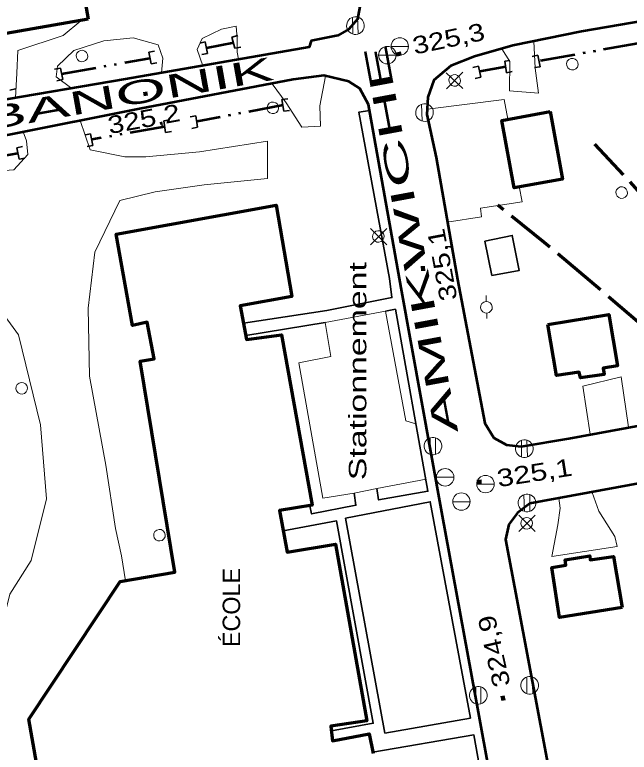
# Model space of a CAD drawing. Extents: x 240591 to 242335, y 5323482 to 5326937.
# Drawn here: x 241079.8 to 241185.4, y 5324850.8 to 5324977.7 of the extents above; entities that cross this region are included whole.
import ezdxf
from ezdxf.enums import TextEntityAlignment as Align

# ---------------------------------------------------------------- set-up
doc = ezdxf.new("R2010")
doc.units = 0
doc.header["$LTSCALE"] = 1.2
doc.linetypes.add('DASH_DOUBLE_DOT', pattern=[9.2, 5, -1.2, 0.3, -1.2, 0.3, -1.2])
doc.linetypes.add('LONG_DASHED', pattern=[7.5, 6, -1.5])
for name, color, linetype, lineweight in [('19', 7, 'Continuous', 13), ('21', 7, 'Continuous', 53), ('22', 7, 'LONG_DASHED', 70), ('26', 7, 'Continuous', 35), ('3', 7, 'Continuous', 140), ('31', 7, 'Continuous', 70), ('36', 7, 'Continuous', 13), ('4', 7, 'DASH_DOUBLE_DOT', 53), ('52', 7, 'Continuous', 13)]:
    doc.layers.add(name, color=color, linetype=linetype, lineweight=lineweight)

msp = doc.modelspace()

# ---------------------------------------------------------------- linework, layer by layer
at = {"layer": '19'}
for points in [[(241079.9, 5324963.4), (241080.1, 5324967.6), (241080.3, 5324971.5), (241088.1, 5324974.1), (241091.1, 5324976.6), (241091.1, 5324976.7)], [(241112.1, 5324968.9), (241111.1, 5324971.7), (241112, 5324973.6), (241115.3, 5324975.2), (241117.8, 5324975.7), (241118, 5324973.6), (241118, 5324971.2), (241118.2, 5324970)], [(241089.6, 5324965), (241086.9, 5324967), (241087.1, 5324968.8), (241089.9, 5324971.5), (241095.1, 5324973.2), (241100.1, 5324973.7), (241104.4, 5324972.5), (241105.2, 5324970.2), (241105, 5324967.7)], [(241169, 5324973.1), (241169.2, 5324968.5), (241169.8, 5324964.2), (241164.8, 5324964.6), (241164.9, 5324969.6), (241163.5, 5324971.8)], [(241133.2, 5324967.1), (241132.2, 5324962), (241132.3, 5324958.5), (241129.1, 5324958.3), (241126.4, 5324962.5), (241124, 5324965.8)], [(241150.7, 5324961.4), (241163.9, 5324963.1), (241164.5, 5324959.7)], [(241091, 5324959.5), (241092.7, 5324954.4), (241098.7, 5324953.2), (241102.3, 5324953.2), (241111.5, 5324954.1), (241123.2, 5324955.9), (241123.2, 5324949.5), (241112.3, 5324948.4), (241103.9, 5324947.2), (241097.8, 5324945.7)], [(241066.2, 5324954.9), (241068, 5324951.1), (241073.2, 5324950.5), (241079.6, 5324951), (241082, 5324953.6), (241081.8, 5324956), (241081.2, 5324957.5)], [(241166.5, 5324948.1), (241167, 5324945.5), (241159.8, 5324944.4), (241160, 5324942.9), (241154.1, 5324942)], [(241097.8, 5324945.7), (241093.5, 5324936.8), (241092.4, 5324927.2), (241092.6, 5324915.5), (241095.4, 5324900.2), (241097.1, 5324889.3), (241098.1, 5324884.6), (241098.8, 5324880.3)], [(241075.5, 5324941.5), (241076.7, 5324934.6), (241076.5, 5324927.9), (241080.4, 5324922.6), (241084.2, 5324907.1), (241085.2, 5324894.4), (241082.6, 5324883.8), (241078.9, 5324878), (241076.7, 5324869.2), (241076, 5324856.2), (241076.8, 5324843.7), (241077, 5324835.7), (241077.1, 5324826.8), (241077.4, 5324818)], [(241178.7, 5324905.5), (241177.4, 5324913.8), (241184, 5324915.4), (241185.3, 5324906.7)], [(241179, 5324895.5), (241180.2, 5324892.3), (241182.9, 5324887.9), (241183.3, 5324886.2), (241172.1, 5324884.5), (241173.1, 5324889.9), (241173.5, 5324892.8), (241173.3, 5324894.5)]]:
    msp.add_lwpolyline(points, dxfattribs=at)
at = {"layer": '21'}
for points in [[(241060.9, 5325030.7), (241094, 5325036.4), (241114.9, 5325040.2), (241130.2, 5325042.8), (241134.5, 5325040.3), (241135.6, 5325038.3), (241136.6, 5325024.1), (241139.2, 5324979.7), (241138.7, 5324976.9), (241137.2, 5324975.2), (241135.3, 5324974.1), (241130.7, 5324973.2), (241130.4, 5324972.1), (241098.8, 5324966.6), (241075.9, 5324962.7)], [(241272, 5324952.9), (241262, 5324986.1), (241258.6, 5324988.2), (241254.5, 5324988.5), (241240.4, 5324986.1), (241209.7, 5324980.4), (241177.2, 5324974.8), (241165.4, 5324972.4), (241158.8, 5324970.5), (241154.7, 5324968.9), (241151.8, 5324966.4), (241150.8, 5324963.5), (241150.6, 5324960.5), (241152.2, 5324953.1), (241155.9, 5324932.1)], [(241146.2, 5324930.7), (241140.6, 5324962.2), (241139.1, 5324965), (241137.2, 5324966.2), (241132.9, 5324967.2), (241127.6, 5324966.5), (241101.2, 5324961.5), (241078.8, 5324957), (241046.6, 5324951.6), (241029.4, 5324948.7), (241025.8, 5324947.9), (241023.9, 5324946.7), (241023.1, 5324945.8), (241022.8, 5324944.1)], [(241155.9, 5324932.1), (241160.6, 5324907.4), (241162.1, 5324904.9), (241164.3, 5324903.7), (241166.8, 5324903.4), (241175, 5324904.8), (241207.1, 5324910.7), (241234.4, 5324915.6), (241273.7, 5324922.7), (241275.7, 5324923.8), (241277.1, 5324925.6), (241278.4, 5324929.2)], [(241184.4, 5324723.6), (241184.3, 5324723.9), (241183.8, 5324726), (241180.3, 5324744.6), (241173.9, 5324779.1), (241167.8, 5324812.1), (241159.6, 5324857.1), (241153.2, 5324892.1), (241146.2, 5324930.7)], [(241283.2, 5324909.1), (241281.1, 5324911.9), (241278.1, 5324913.5), (241273.7, 5324913), (241249.5, 5324908.6), (241202.6, 5324899.9), (241168.3, 5324893.6), (241166.2, 5324892), (241164.7, 5324890), (241164.1, 5324887.4), (241165.7, 5324879.2), (241174.6, 5324831.6), (241176.7, 5324829.5), (241178.9, 5324828.5), (241182.8, 5324828.5), (241200.3, 5324831.7), (241239.9, 5324838.8), (241289.9, 5324848.1), (241291.7, 5324849.9), (241292.5, 5324851.5), (241293.4, 5324855.4)]]:
    msp.add_lwpolyline(points, dxfattribs=at)
at = {"layer": '22', "linetype": 'Continuous', "lineweight": 35}
msp.add_line((241133.1, 5324924.7), (241119.5, 5324922.5), dxfattribs=at)
for points in [[(241144.2, 5324932.3), (241138.9, 5324960.9), (241140.8, 5324961.2)], [(241119.1, 5324924.6), (241133.4, 5324926.8), (241144.6, 5324929), (241144.2, 5324932.3)], [(241142, 5324896.2), (241142.3, 5324894.2), (241150.8, 5324895.7), (241145.2, 5324927), (241143.5, 5324926.7)], [(241130.5, 5324893.2), (241130.8, 5324891.8), (241138.4, 5324893.3), (241138.1, 5324895.4)], [(241134.2, 5324854.5), (241141.4, 5324855.8), (241135.1, 5324890.6), (241125.9, 5324888.9)], [(241184.1, 5324724.9), (241182.1, 5324724.6), (241172.5, 5324777.8), (241161.8, 5324836.5), (241158.7, 5324853.8), (241141.3, 5324850.8)]]:
    msp.add_lwpolyline(points, dxfattribs=at)
at = {"layer": '22'}
for points in [[(241179.4, 5324955.4), (241185.5, 5324948.9), (241190.6, 5324943.1), (241195.7, 5324938.9), (241201, 5324933.5), (241205.6, 5324927.3)], [(241192.9, 5324918), (241192.9, 5324918), (241187.3, 5324924.5), (241178.6, 5324931.9), (241170.8, 5324938.5), (241162.8, 5324944.9)]]:
    msp.add_lwpolyline(points, dxfattribs=at)
at = {"layer": '22', "linetype": 'Continuous', "lineweight": 35}
msp.add_lwpolyline([(241136.6, 5324891.1), (241151.2, 5324893.9), (241158.1, 5324856.7), (241143.4, 5324854.1)], close=True, dxfattribs=at)
at = {"layer": '26'}
for p, q in [((241117.1, 5324973.8), (241118.1, 5324974.1)), ((241117.6, 5324971.9), (241117.1, 5324973.8)), ((241112.5, 5324973), (241111.6, 5324972.8)), ((241112.5, 5324973), (241112.9, 5324971)), ((241117.6, 5324971.9), (241118.6, 5324972.1)), ((241102.8, 5324971.2), (241103.8, 5324971.4)), ((241103.2, 5324969.2), (241102.8, 5324971.2)), ((241112.9, 5324971), (241111.9, 5324970.8)), ((241164, 5324969.7), (241164.9, 5324969.8)), ((241164.3, 5324967.7), (241164, 5324969.7)), ((241169.7, 5324970.7), (241168.7, 5324970.5)), ((241169.7, 5324970.7), (241170.1, 5324968.7)), ((241087.6, 5324968.5), (241086.6, 5324968.3)), ((241087.6, 5324968.5), (241088, 5324966.5)), ((241103.2, 5324969.2), (241104.2, 5324969.4)), ((241159.5, 5324968.8), (241158.5, 5324968.6)), ((241159.5, 5324968.8), (241159.9, 5324966.9)), ((241170.1, 5324968.7), (241169.1, 5324968.6)), ((241164.3, 5324967.7), (241165.3, 5324967.9)), ((241088, 5324966.5), (241087, 5324966.3)), ((241159.9, 5324966.9), (241158.9, 5324966.7)), ((241078.9, 5324964.7), (241079.9, 5324964.9)), ((241125.7, 5324963.1), (241126.7, 5324963.2)), ((241126, 5324961.1), (241125.7, 5324963.1)), ((241126, 5324961.1), (241127, 5324961.2)), ((241105.4, 5324959.4), (241106.4, 5324959.6)), ((241105.7, 5324957.4), (241105.4, 5324959.4)), ((241110.9, 5324960.3), (241109.9, 5324960.1)), ((241110.9, 5324960.3), (241111.2, 5324958.3)), ((241111.2, 5324958.3), (241110.2, 5324958.1)), ((241092.8, 5324957.2), (241091.9, 5324957)), ((241092.8, 5324957.2), (241093.2, 5324955.2)), ((241105.7, 5324957.4), (241106.7, 5324957.6)), ((241080.1, 5324954.8), (241081.1, 5324955)), ((241080.5, 5324952.8), (241080.1, 5324954.8)), ((241093.2, 5324955.2), (241092.2, 5324955)), ((241080.5, 5324952.8), (241081.5, 5324953))]:
    msp.add_line(p, q, dxfattribs=at)
at = {"layer": '3'}
for p, q in [((241145.4, 5324970.8), (241146.2, 5324971)), ((241101.9, 5324964), (241102.6, 5324964.1)), ((241150, 5324933.6), (241149.9, 5324934.4)), ((241159.2, 5324897.3), (241160, 5324897.4)), ((241163.8, 5324859.7), (241163.6, 5324860.5))]:
    msp.add_line(p, q, dxfattribs=at)
at = {"layer": '31'}
for points in [[(241092.4, 5324976.9), (241076.9, 5324974.2), (241075.4, 5324982.8), (241090.9, 5324985.4)], [(241171.8, 5324961), (241173.9, 5324949.4), (241165.6, 5324947.9), (241163.5, 5324959.5)], [(241171.4, 5324924.4), (241181.9, 5324926.1), (241183.4, 5324917.3), (241180.9, 5324916.9), (241181.1, 5324915.8), (241177, 5324915.2), (241176.8, 5324916.2), (241172.9, 5324915.6)], [(241184.2, 5324875.7), (241173.4, 5324874), (241172.1, 5324882.6), (241174.5, 5324883), (241174.4, 5324883.9), (241178.6, 5324884.6), (241178.7, 5324883.9), (241182.7, 5324884.5)]]:
    msp.add_lwpolyline(points, close=True, dxfattribs=at)
msp.add_lwpolyline([(241088.6, 5324819.9), (241082.2, 5324856.5), (241097.9, 5324880.2), (241107.3, 5324881.8), (241101.3, 5324918.1), (241103.7, 5324918.5), (241102.5, 5324924.8), (241100, 5324924.2), (241097.2, 5324939.9), (241124.7, 5324944.9), (241127.4, 5324929.2), (241118.5, 5324927.6), (241119.6, 5324921.8), (241125.6, 5324922.6), (241130.9, 5324893.3), (241125.3, 5324892.4), (241126.6, 5324885.2), (241134.9, 5324886.6), (241140.3, 5324856.2), (241134.1, 5324855.3), (241134.4, 5324852.8), (241140.7, 5324854), (241141.4, 5324850.6)], dxfattribs=at)
at = {"layer": '31', "lineweight": 35}
msp.add_lwpolyline([(241161.8, 5324932.8), (241160.6, 5324938.7), (241165.3, 5324939.7), (241166.5, 5324933.7)], close=True, dxfattribs=at)
at = {"layer": '36'}
for p, q in [((241137.8, 5324977.2), (241137.9, 5324974.3)), ((241138.8, 5324974.4), (241138.7, 5324977.3)), ((241144.4, 5324972.2), (241147.4, 5324972.2)), ((241142.3, 5324970.7), (241145.3, 5324970.7)), ((241156.8, 5324965), (241153.9, 5324967.7)), ((241154, 5324964.9), (241156.8, 5324967.8)), ((241149.7, 5324962.3), (241149.8, 5324959.4)), ((241150.7, 5324959.4), (241150.6, 5324962.3)), ((241143.7, 5324938.1), (241140.9, 5324940.9)), ((241143.7, 5324940.9), (241140.9, 5324938.1)), ((241160.8, 5324929.4), (241160.8, 5324928.4)), ((241160.9, 5324925.4), (241160.9, 5324926.4)), ((241151.2, 5324904.9), (241151.2, 5324902)), ((241152.1, 5324902), (241152.1, 5324904.9)), ((241166.9, 5324904.5), (241166.9, 5324901.6)), ((241167.9, 5324901.6), (241167.8, 5324904.5)), ((241152.2, 5324898.1), (241155.2, 5324898.1)), ((241159.2, 5324896.9), (241162.2, 5324896.9)), ((241167.3, 5324895.1), (241167.4, 5324892.2)), ((241168.3, 5324892.3), (241168.3, 5324895.2)), ((241155, 5324893.9), (241158, 5324893.9)), ((241169.2, 5324888.8), (241166.4, 5324891.6)), ((241169.2, 5324891.6), (241166.4, 5324888.8)), ((241167.8, 5324863.7), (241167.8, 5324860.9)), ((241168.8, 5324860.9), (241168.7, 5324863.8)), ((241159, 5324862), (241159, 5324859.1)), ((241159.9, 5324859.2), (241159.9, 5324862.1))]:
    msp.add_line(p, q, dxfattribs=at)
for centre in [(241145.949, 5324972.212), (241143.809, 5324970.712), (241153.749, 5324898.092), (241160.689, 5324896.932), (241156.549, 5324893.932)]:
    msp.add_circle(centre, 1.5, dxfattribs=at)
for centre, major_axis, ratio in [((241138.324, 5324975.797), (-0.396, 1.465), 0.99964), ((241091.323, 5324970.56), (0.261, -0.965), 0.99964), ((241175.613, 5324969.17), (0.261, -0.965), 0.99964), ((241155.394, 5324966.367), (-0.261, 0.965), 0.99964), ((241124.123, 5324961.64), (0.261, -0.965), 0.99964), ((241150.204, 5324960.837), (-0.396, 1.465), 0.99964), ((241184.103, 5324947.07), (0.261, -0.965), 0.99964), ((241142.282, 5324939.525), (-0.463, 0.886), 0.999959), ((241160.852, 5324927.349), (-0.463, 0.886), 0.999959), ((241080.96, 5324913.423), (-0.463, 0.886), 0.999959), ((241151.645, 5324903.457), (-0.703, 1.345), 0.999959), ((241167.375, 5324903.027), (-0.703, 1.345), 0.999959), ((241167.815, 5324893.697), (-0.703, 1.345), 0.999959), ((241167.772, 5324890.195), (-0.463, 0.886), 0.999959), ((241104.64, 5324888.143), (-0.463, 0.886), 0.999959), ((241168.285, 5324862.317), (-0.703, 1.345), 0.999959), ((241159.445, 5324860.597), (-0.703, 1.345), 0.999959)]:
    msp.add_ellipse(centre, major_axis=major_axis, ratio=ratio, dxfattribs=at)
at = {"layer": '4'}
for p, q in [((241112.7, 5324972), (241117.4, 5324972.9)), ((241186.9, 5324972.7), (241169.9, 5324969.7)), ((241087.8, 5324967.5), (241103, 5324970.2)), ((241164.2, 5324968.7), (241159.7, 5324967.9)), ((241125.9, 5324962.1), (241111.1, 5324959.3)), ((241105.5, 5324958.4), (241093, 5324956.2)), ((241080.3, 5324953.8), (241068.6, 5324951.8))]:
    msp.add_line(p, q, dxfattribs=at)
at = {"layer": '52'}
msp.add_lwpolyline([(241150.5, 5324897.8), (241142, 5324896.2), (241138.1, 5324895.4), (241132.7, 5324894.5), (241128.6, 5324917.8), (241134.1, 5324918.9), (241133.1, 5324924.7), (241143.5, 5324926.7), (241147, 5324907.8), (241148.7, 5324907.3)], dxfattribs=at)

# ---------------------------------------------------------------- texts
at = {"layer": '21'}
for s, rotation, width, p in [('AMIKWICHE', 100.512, 2.2, (241156, 5324905.9)), ('WABANONIK', 10.065, 2.1, (241056.9, 5324954.5))]:
    msp.add_text(s, height=4, rotation=rotation, dxfattribs=dict(at, width=width)).set_placement(p)
at = {"layer": '3'}
for s, height, rotation, width, p in [('325,3', 3, 11.828, 1.25, (241148.5, 5324970.8)), ('325,1', 3, 8.914, 1.3, (241162.9, 5324896.4)), ('324,9', 2.999, 102.752, 1.25, (241165, 5324862.4))]:
    msp.add_text(s, height=height, rotation=rotation, dxfattribs=dict(at, width=width)).set_placement(p)
at = {"layer": '3', "width": 1.25}
for s, height, rotation, p in [('325,2', 3, 10.498, (241102.227, 5324958.272)), ('325,1', 2.999, 100.623, (241154.714, 5324934.924))]:
    msp.add_text(s, height=height, rotation=rotation, dxfattribs=at).set_placement(p, align=Align.CENTER)
at = {"layer": '31'}
msp.add_text('ÉCOLE', height=3, rotation=90, dxfattribs=at).set_placement((241118.5, 5324868.9))
at = {"layer": '52', "width": 1.45}
msp.add_text('Stationnement', height=3, rotation=90, dxfattribs=at).set_placement((241140.2, 5324897.6))

doc.saveas('drawing.dxf')
